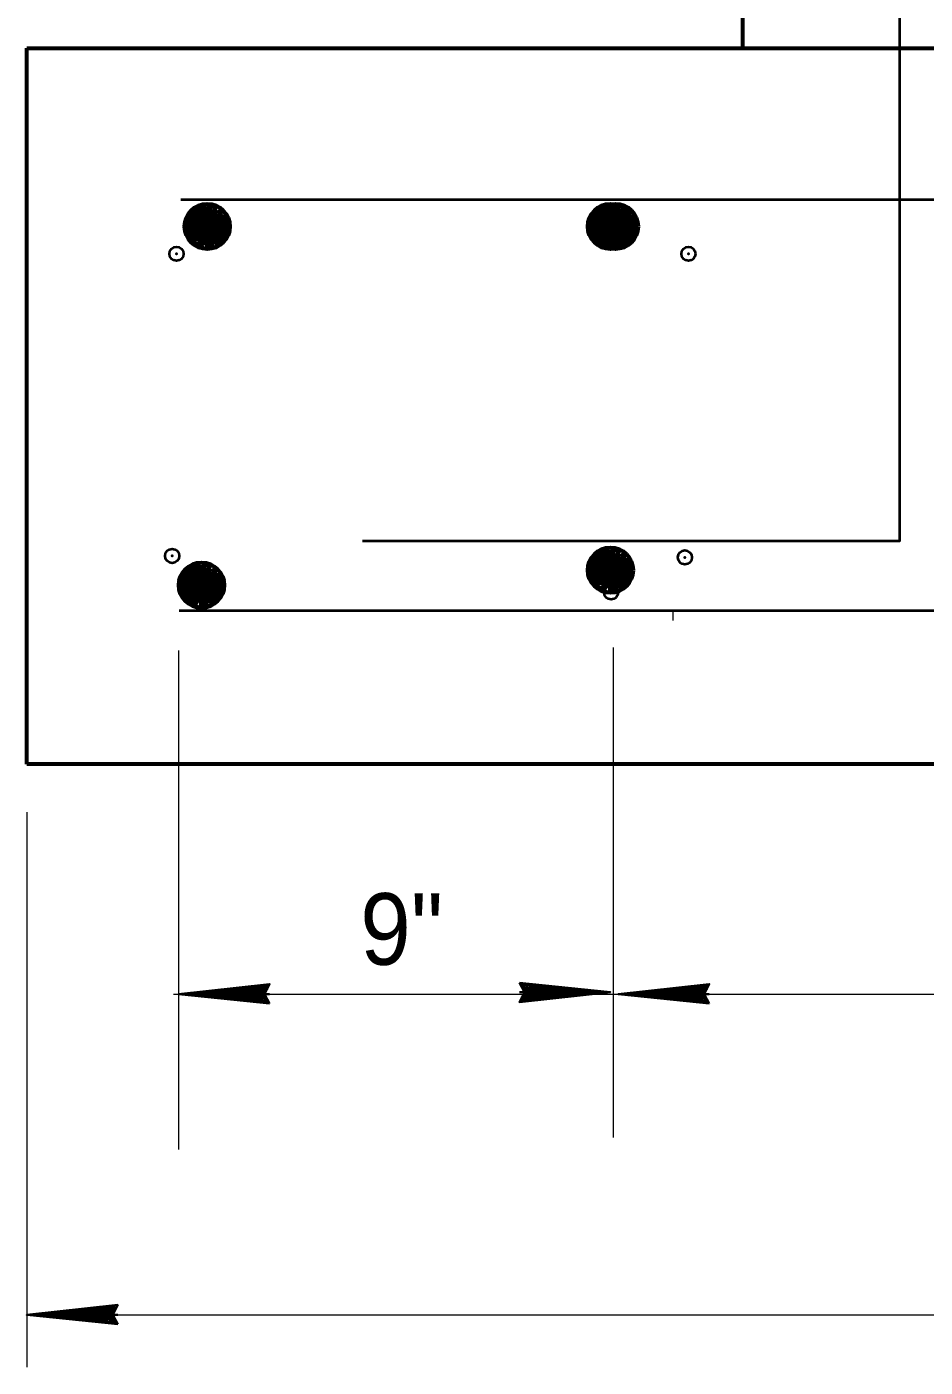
# Model space of a CAD drawing. Extents: x 14.14 to 17.34, y -1.61 to 0.38.
# Drawn here: x 15.5065 to 15.611, y -0.0853 to 0.0707 of the extents above; entities that cross this region are included whole.
import ezdxf
from ezdxf.enums import TextEntityAlignment as Align

# ---------------------------------------------------------------- set-up
doc = ezdxf.new("R2010")
doc.units = 0
doc.header["$LTSCALE"] = 0.0033
doc.header["$PDMODE"] = 32
doc.header["$PDSIZE"] = 0.00165
doc.layers.add('1', color=7, linetype='Continuous', lineweight=40)

msp = doc.modelspace()

# ---------------------------------------------------------------- linework, layer by layer
at = {"layer": '1', "lineweight": 60}
for p, q in [((15.5065, -0.015167), (15.5065, 0.068167)), ((15.589833, 0.068167), (15.652333, 0.068167)), ((15.525667, 0.049), (15.5255, 0.046083)), ((15.525917, 0.049), (15.525667, 0.046083)), ((15.526083, 0.049), (15.525917, 0.046)), ((15.52625, 0.049), (15.526, 0.046)), ((15.526417, 0.049), (15.52625, 0.046)), ((15.526667, 0.049), (15.5265, 0.046)), ((15.526917, 0.049), (15.526667, 0.046)), ((15.527, 0.048917), (15.526833, 0.046)), ((15.527167, 0.048917), (15.527, 0.046)), ((15.527333, 0.048917), (15.527167, 0.046)), ((15.527583, 0.048917), (15.527333, 0.046)), ((15.52775, 0.048917), (15.527583, 0.046)), ((15.528, 0.048833), (15.52775, 0.045917)), ((15.52825, 0.048833), (15.528, 0.045917)), ((15.528417, 0.048833), (15.52825, 0.045917)), ((15.5285, 0.048833), (15.528333, 0.045917)), ((15.528667, 0.048833), (15.5285, 0.045917)), ((15.52875, 0.048833), (15.528583, 0.045917)), ((15.529, 0.04875), (15.52875, 0.045833)), ((15.529167, 0.04875), (15.529, 0.045833)), ((15.529333, 0.04875), (15.529083, 0.045833)), ((15.5295, 0.04875), (15.529333, 0.045833)), ((15.52975, 0.04875), (15.529583, 0.045833)), ((15.53, 0.046833), (15.529833, 0.048667)), ((15.572583, 0.049), (15.572417, 0.046083)), ((15.572833, 0.049), (15.572583, 0.046083)), ((15.573, 0.049), (15.572833, 0.046)), ((15.573167, 0.049), (15.572917, 0.046)), ((15.573167, 0.049), (15.573, 0.046083)), ((15.573417, 0.049), (15.573167, 0.046083)), ((15.573333, 0.049), (15.573167, 0.046)), ((15.573583, 0.049), (15.573417, 0.046)), ((15.573583, 0.049), (15.573417, 0.046)), ((15.57375, 0.049), (15.5735, 0.046)), ((15.573833, 0.049), (15.573583, 0.046)), ((15.573917, 0.049), (15.57375, 0.046)), ((15.573917, 0.048917), (15.57375, 0.046)), ((15.574083, 0.048917), (15.573917, 0.046)), ((15.574167, 0.049), (15.574, 0.046)), ((15.57425, 0.048917), (15.574083, 0.046)), ((15.574417, 0.049), (15.574167, 0.046)), ((15.5745, 0.048917), (15.57425, 0.046)), ((15.5745, 0.048917), (15.574333, 0.046)), ((15.574667, 0.048917), (15.5745, 0.046)), ((15.574667, 0.048917), (15.5745, 0.046)), ((15.574833, 0.048917), (15.574667, 0.046)), ((15.574917, 0.048833), (15.574667, 0.045917)), ((15.575083, 0.048917), (15.574833, 0.046)), ((15.575167, 0.048833), (15.574917, 0.045917)), ((15.57525, 0.048917), (15.575083, 0.046)), ((15.575333, 0.048833), (15.575167, 0.045917)), ((15.5755, 0.048833), (15.57525, 0.045917)), ((15.575417, 0.048833), (15.57525, 0.045917)), ((15.575583, 0.048833), (15.575417, 0.045917)), ((15.57575, 0.048833), (15.5755, 0.045917)), ((15.575667, 0.048833), (15.5755, 0.045917)), ((15.575917, 0.04875), (15.575667, 0.045833)), ((15.575917, 0.048833), (15.57575, 0.045917)), ((15.576, 0.048833), (15.575833, 0.045917)), ((15.576083, 0.04875), (15.575917, 0.045833)), ((15.576167, 0.048833), (15.576, 0.045917)), ((15.57625, 0.04875), (15.576, 0.045833)), ((15.57625, 0.048833), (15.576083, 0.045917)), ((15.5765, 0.04875), (15.57625, 0.045833)), ((15.576417, 0.04875), (15.57625, 0.045833)), ((15.576667, 0.04875), (15.5765, 0.045833)), ((15.576667, 0.04875), (15.5765, 0.045833)), ((15.576833, 0.04875), (15.576583, 0.045833)), ((15.576917, 0.046833), (15.57675, 0.048667)), ((15.577, 0.04875), (15.576833, 0.045833)), ((15.57725, 0.04875), (15.577083, 0.045833)), ((15.5775, 0.046833), (15.577333, 0.048667)), ((15.53, 0.046833), (15.52525, 0.046083)), ((15.576917, 0.046833), (15.572167, 0.046083)), ((15.5775, 0.046833), (15.57275, 0.046083)), ((15.572583, 0.009), (15.572417, 0.006083)), ((15.572833, 0.009), (15.572583, 0.006083)), ((15.573, 0.009), (15.572833, 0.006)), ((15.573167, 0.009), (15.572917, 0.006)), ((15.573333, 0.009), (15.573167, 0.006)), ((15.573583, 0.009), (15.573417, 0.006)), ((15.573833, 0.009), (15.573583, 0.006)), ((15.573917, 0.008917), (15.57375, 0.006)), ((15.574083, 0.008917), (15.573917, 0.006)), ((15.57425, 0.008917), (15.574083, 0.006)), ((15.5745, 0.008917), (15.57425, 0.006)), ((15.574667, 0.008917), (15.5745, 0.006)), ((15.574917, 0.008833), (15.574667, 0.005917)), ((15.575167, 0.008833), (15.574917, 0.005917)), ((15.575333, 0.008833), (15.575167, 0.005917)), ((15.575417, 0.008833), (15.57525, 0.005917)), ((15.575583, 0.008833), (15.575417, 0.005917)), ((15.575667, 0.008833), (15.5755, 0.005917)), ((15.575917, 0.00875), (15.575667, 0.005833)), ((15.576083, 0.00875), (15.575917, 0.005833)), ((15.57625, 0.00875), (15.576, 0.005833)), ((15.576417, 0.00875), (15.57625, 0.005833)), ((15.576667, 0.00875), (15.5765, 0.005833)), ((15.576917, 0.006833), (15.57675, 0.008667)), ((15.525, 0.00725), (15.524833, 0.004333)), ((15.52525, 0.00725), (15.525, 0.004333)), ((15.525417, 0.00725), (15.52525, 0.00425)), ((15.525583, 0.00725), (15.525333, 0.00425)), ((15.52575, 0.00725), (15.525583, 0.00425)), ((15.526, 0.00725), (15.525833, 0.00425)), ((15.52625, 0.00725), (15.526, 0.00425)), ((15.526333, 0.007167), (15.526167, 0.00425)), ((15.5265, 0.007167), (15.526333, 0.00425)), ((15.526667, 0.007167), (15.5265, 0.00425)), ((15.526917, 0.007167), (15.526667, 0.00425)), ((15.527083, 0.007167), (15.526917, 0.00425)), ((15.527333, 0.007083), (15.527083, 0.004167)), ((15.527583, 0.007083), (15.527333, 0.004167)), ((15.52775, 0.007083), (15.527583, 0.004167)), ((15.527833, 0.007083), (15.527667, 0.004167)), ((15.528, 0.007083), (15.527833, 0.004167)), ((15.528083, 0.007083), (15.527917, 0.004167)), ((15.528333, 0.007), (15.528083, 0.004083)), ((15.5285, 0.007), (15.528333, 0.004083)), ((15.528667, 0.007), (15.528417, 0.004083)), ((15.528833, 0.007), (15.528667, 0.004083)), ((15.529083, 0.007), (15.528917, 0.004083)), ((15.529333, 0.005083), (15.529167, 0.006917)), ((15.576917, 0.006833), (15.572167, 0.006083)), ((15.529333, 0.005083), (15.524583, 0.004333))]:
    msp.add_line(p, q, dxfattribs=at)
at = {"layer": '1'}
for p, q in [((15.524417, 0.050583), (15.822167, 0.050583)), ((15.525417, 0.049), (15.53, 0.046833)), ((15.525667, 0.048583), (15.529583, 0.047833)), ((15.525667, 0.048417), (15.529583, 0.047667)), ((15.52575, 0.049), (15.529667, 0.048333)), ((15.52575, 0.048833), (15.529667, 0.048083)), ((15.525833, 0.049333), (15.529667, 0.048667)), ((15.52775, 0.0485), (15.529083, 0.0495)), ((15.529833, 0.048667), (15.528583, 0.049833)), ((15.572333, 0.049), (15.576917, 0.046833)), ((15.572583, 0.048583), (15.5765, 0.047833)), ((15.572583, 0.048417), (15.5765, 0.047667)), ((15.572667, 0.049), (15.576583, 0.048333)), ((15.572667, 0.048833), (15.576583, 0.048083)), ((15.57275, 0.049333), (15.576583, 0.048667)), ((15.572917, 0.049), (15.5775, 0.046833)), ((15.573167, 0.048583), (15.577083, 0.047833)), ((15.573167, 0.048417), (15.577083, 0.047667)), ((15.57325, 0.049), (15.577167, 0.048333)), ((15.57325, 0.048833), (15.577167, 0.048083)), ((15.573333, 0.049333), (15.577167, 0.048667)), ((15.574667, 0.0485), (15.576, 0.0495)), ((15.57525, 0.0485), (15.576583, 0.0495)), ((15.57675, 0.048667), (15.5755, 0.049833)), ((15.577333, 0.048667), (15.576083, 0.049833)), ((15.525417, 0.047167), (15.529333, 0.046417)), ((15.5255, 0.047583), (15.529333, 0.046833)), ((15.5255, 0.047417), (15.529333, 0.046667)), ((15.525583, 0.048), (15.529417, 0.047333)), ((15.525583, 0.047833), (15.529417, 0.047083)), ((15.525667, 0.048167), (15.5295, 0.047417)), ((15.572333, 0.047167), (15.57625, 0.046417)), ((15.572417, 0.047583), (15.57625, 0.046833)), ((15.572417, 0.047417), (15.57625, 0.046667)), ((15.5725, 0.048), (15.576333, 0.047333)), ((15.5725, 0.047833), (15.576333, 0.047083)), ((15.572583, 0.048167), (15.576417, 0.047417)), ((15.572917, 0.047167), (15.576833, 0.046417)), ((15.573, 0.047583), (15.576833, 0.046833)), ((15.573, 0.047417), (15.576833, 0.046667)), ((15.573083, 0.048), (15.576917, 0.047333)), ((15.573083, 0.047833), (15.576917, 0.047083)), ((15.573167, 0.048167), (15.577, 0.047417)), ((15.52525, 0.04625), (15.529083, 0.0455)), ((15.52525, 0.046083), (15.529083, 0.045333)), ((15.525333, 0.04675), (15.52925, 0.046)), ((15.525333, 0.046583), (15.529167, 0.045833)), ((15.525333, 0.046333), (15.529167, 0.045667)), ((15.529583, 0.045833), (15.525833, 0.045417)), ((15.572167, 0.04625), (15.576, 0.0455)), ((15.572167, 0.046083), (15.576, 0.045333)), ((15.57225, 0.04675), (15.576167, 0.046)), ((15.57225, 0.046583), (15.576083, 0.045833)), ((15.57225, 0.046333), (15.576083, 0.045667)), ((15.57275, 0.04625), (15.576583, 0.0455)), ((15.57275, 0.046083), (15.576583, 0.045333)), ((15.5765, 0.045833), (15.57275, 0.045417)), ((15.572833, 0.04675), (15.57675, 0.046)), ((15.572833, 0.046583), (15.576667, 0.045833)), ((15.572833, 0.046333), (15.576667, 0.045667)), ((15.577083, 0.045833), (15.573333, 0.045417)), ((15.574667, 0.0085), (15.576, 0.0095)), ((15.57675, 0.008667), (15.5755, 0.009833)), ((15.529167, 0.006917), (15.527917, 0.008083)), ((15.572333, 0.009), (15.576917, 0.006833)), ((15.5725, 0.008), (15.576333, 0.007333)), ((15.5725, 0.007833), (15.576333, 0.007083)), ((15.572583, 0.008583), (15.5765, 0.007833)), ((15.572583, 0.008417), (15.5765, 0.007667)), ((15.572583, 0.008167), (15.576417, 0.007417)), ((15.572667, 0.009), (15.576583, 0.008333)), ((15.572667, 0.008833), (15.576583, 0.008083)), ((15.57275, 0.009333), (15.576583, 0.008667)), ((15.52475, 0.00725), (15.529333, 0.005083)), ((15.524917, 0.00625), (15.52875, 0.005583)), ((15.525, 0.006833), (15.528917, 0.006083)), ((15.525, 0.006667), (15.528917, 0.005917)), ((15.525, 0.006417), (15.528833, 0.005667)), ((15.525083, 0.00725), (15.529, 0.006583)), ((15.525083, 0.007083), (15.529, 0.006333)), ((15.525167, 0.007583), (15.529, 0.006917)), ((15.527083, 0.00675), (15.528417, 0.00775)), ((15.572167, 0.00625), (15.576, 0.0055)), ((15.57225, 0.00675), (15.576167, 0.006)), ((15.57225, 0.006583), (15.576083, 0.005833)), ((15.57225, 0.006333), (15.576083, 0.005667)), ((15.572333, 0.007167), (15.57625, 0.006417)), ((15.572417, 0.007583), (15.57625, 0.006833)), ((15.572417, 0.007417), (15.57625, 0.006667)), ((15.524667, 0.005), (15.528583, 0.00425)), ((15.524667, 0.004833), (15.5285, 0.004083)), ((15.52475, 0.005417), (15.528667, 0.004667)), ((15.524833, 0.005833), (15.528667, 0.005083)), ((15.524833, 0.005667), (15.528667, 0.004917)), ((15.524917, 0.006083), (15.52875, 0.005333)), ((15.572167, 0.006083), (15.576, 0.005333)), ((15.5765, 0.005833), (15.57275, 0.005417)), ((15.524583, 0.0045), (15.528417, 0.00375)), ((15.524583, 0.004333), (15.528417, 0.003583)), ((15.524667, 0.004583), (15.5285, 0.003917)), ((15.528917, 0.004083), (15.525167, 0.003667)), ((15.52425, 0.00275), (15.821917, 0.00275))]:
    msp.add_line(p, q, dxfattribs=at)
at = {"layer": '1', "lineweight": 13}
for p, q in [((15.581667, 0.00275), (15.581667, 0.001583)), ((15.524167, -0.001917), (15.524167, -0.06)), ((15.57475, -0.001583), (15.57475, -0.058583)), ((15.5065, -0.02075), (15.5065, -0.085333)), ((15.523583, -0.041917), (15.820833, -0.041917)), ((15.511083, -0.07925), (15.837333, -0.07925))]:
    msp.add_line(p, q, dxfattribs=at)
at = {"layer": '1', "lineweight": 35}
for p, q in [((15.53475, -0.041917), (15.524167, -0.041917)), ((15.5345, -0.04275), (15.526667, -0.04175)), ((15.5345, -0.04275), (15.526667, -0.041917)), ((15.5345, -0.042917), (15.526667, -0.042)), ((15.5345, -0.042917), (15.526667, -0.042)), ((15.5345, -0.042833), (15.526667, -0.042)), ((15.5345, -0.040833), (15.527167, -0.041667)), ((15.5345, -0.041), (15.527167, -0.04175)), ((15.5345, -0.041083), (15.527167, -0.041917)), ((15.534583, -0.04125), (15.52725, -0.042)), ((15.563833, -0.041667), (15.574417, -0.041667)), ((15.564, -0.042333), (15.571333, -0.041583)), ((15.564083, -0.040667), (15.571917, -0.041583)), ((15.564083, -0.040667), (15.571917, -0.041583)), ((15.564083, -0.04075), (15.571917, -0.041583)), ((15.564083, -0.040833), (15.571917, -0.041667)), ((15.564083, -0.040833), (15.571917, -0.041833)), ((15.564083, -0.0425), (15.571417, -0.041667)), ((15.564083, -0.042583), (15.571417, -0.041833)), ((15.564083, -0.04275), (15.571417, -0.041917)), ((15.585917, -0.041917), (15.575333, -0.041917)), ((15.585667, -0.04275), (15.577833, -0.04175)), ((15.585667, -0.04275), (15.577833, -0.041917)), ((15.585667, -0.042917), (15.577833, -0.042)), ((15.585667, -0.042917), (15.577833, -0.042)), ((15.585667, -0.042833), (15.577833, -0.042)), ((15.585667, -0.040833), (15.578333, -0.041667)), ((15.585667, -0.041), (15.578333, -0.04175)), ((15.585667, -0.041083), (15.578333, -0.041917)), ((15.58575, -0.04125), (15.578417, -0.042)), ((15.517083, -0.07925), (15.5065, -0.07925)), ((15.516833, -0.080083), (15.509, -0.079083)), ((15.516833, -0.080083), (15.509, -0.07925)), ((15.516833, -0.08025), (15.509, -0.079333)), ((15.516833, -0.08025), (15.509, -0.079333)), ((15.516833, -0.080167), (15.509, -0.079333)), ((15.516833, -0.078167), (15.5095, -0.079)), ((15.516833, -0.078333), (15.5095, -0.079083)), ((15.516833, -0.078417), (15.5095, -0.07925)), ((15.516917, -0.078583), (15.509583, -0.079333))]:
    msp.add_line(p, q, dxfattribs=at)
at = {"layer": '1', "lineweight": 60}
for points in [[(15.5065, 0.068167), (15.589833, 0.068167), (15.589833, 0.172333)], [(15.839833, 0.068167), (15.839833, -0.015167), (15.5065, -0.015167)], [(15.529083, 0.045333), (15.529083, 0.0495), (15.527417, 0.044833), (15.527917, 0.05), (15.525833, 0.045417), (15.526583, 0.049917), (15.528167, 0.044917), (15.525, 0.04825), (15.529833, 0.048667), (15.526583, 0.045), (15.528583, 0.049833), (15.525417, 0.049), (15.52525, 0.046083)], [(15.525833, 0.045417), (15.527333, 0.047667), (15.525167, 0.048583), (15.527167, 0.05), (15.527333, 0.04775), (15.529, 0.045417), (15.525, 0.04775), (15.52775, 0.0485)], [(15.576, 0.045333), (15.576, 0.0495), (15.574333, 0.044833), (15.574833, 0.05), (15.57275, 0.045417), (15.5735, 0.049917), (15.575083, 0.044917), (15.571917, 0.04825), (15.57675, 0.048667), (15.5735, 0.045), (15.5755, 0.049833), (15.572333, 0.049), (15.572167, 0.046083)], [(15.57275, 0.045417), (15.57425, 0.047667), (15.572083, 0.048583), (15.574083, 0.05), (15.57425, 0.04775), (15.575917, 0.045417), (15.571917, 0.04775), (15.574667, 0.0485)], [(15.576583, 0.045333), (15.576583, 0.0495), (15.574917, 0.044833), (15.575417, 0.05), (15.573333, 0.045417), (15.574083, 0.049917), (15.575667, 0.044917), (15.5725, 0.04825), (15.577333, 0.048667), (15.574083, 0.045), (15.576083, 0.049833), (15.572917, 0.049), (15.57275, 0.046083)], [(15.573333, 0.045417), (15.574833, 0.047667), (15.572667, 0.048583), (15.574667, 0.05), (15.574833, 0.04775), (15.5765, 0.045417), (15.5725, 0.04775), (15.57525, 0.0485)], [(15.524833, 0.047333), (15.53, 0.048), (15.525417, 0.049)], [(15.528583, 0.049833), (15.527333, 0.047667), (15.529583, 0.045833)], [(15.57175, 0.047333), (15.576917, 0.048), (15.572333, 0.049)], [(15.572333, 0.047333), (15.5775, 0.048), (15.572917, 0.049)], [(15.5755, 0.049833), (15.57425, 0.047667), (15.5765, 0.045833)], [(15.576083, 0.049833), (15.574833, 0.047667), (15.577083, 0.045833)], [(15.576, 0.005333), (15.576, 0.0095), (15.574333, 0.004833), (15.574833, 0.01), (15.57275, 0.005417), (15.5735, 0.009917), (15.575083, 0.004917), (15.571917, 0.00825), (15.57675, 0.008667), (15.5735, 0.005), (15.5755, 0.009833), (15.572333, 0.009), (15.572167, 0.006083)], [(15.57275, 0.005417), (15.57425, 0.007667), (15.572083, 0.008583), (15.574083, 0.01), (15.57425, 0.00775), (15.575917, 0.005417), (15.571917, 0.00775), (15.574667, 0.0085)], [(15.5755, 0.009833), (15.57425, 0.007667), (15.5765, 0.005833)], [(15.528417, 0.003583), (15.528417, 0.00775), (15.52675, 0.003083), (15.52725, 0.00825), (15.525167, 0.003667), (15.525917, 0.008167), (15.5275, 0.003167), (15.524333, 0.0065), (15.529167, 0.006917), (15.525917, 0.00325), (15.527917, 0.008083), (15.52475, 0.00725), (15.524583, 0.004333)], [(15.525167, 0.003667), (15.526667, 0.005917), (15.5245, 0.006833), (15.5265, 0.00825), (15.526667, 0.006), (15.528333, 0.003667), (15.524333, 0.006), (15.527083, 0.00675)], [(15.527917, 0.008083), (15.526667, 0.005917), (15.528917, 0.004083)], [(15.57175, 0.007333), (15.576917, 0.008), (15.572333, 0.009)], [(15.524167, 0.005583), (15.529333, 0.00625), (15.52475, 0.00725)]]:
    msp.add_lwpolyline(points, dxfattribs=at)
at = {"layer": '1'}
for points in [[(15.545583, 0.010833), (15.608083, 0.010833), (15.608083, 0.123)], [(15.52525, 0.046083), (15.527333, 0.044833), (15.529083, 0.045333), (15.53, 0.046833)], [(15.572167, 0.046083), (15.57425, 0.044833), (15.576, 0.045333), (15.576917, 0.046833)], [(15.57275, 0.046083), (15.574833, 0.044833), (15.576583, 0.045333), (15.5775, 0.046833)], [(15.572167, 0.006083), (15.57425, 0.004833), (15.576, 0.005333), (15.576917, 0.006833)], [(15.524583, 0.004333), (15.526667, 0.003083), (15.528417, 0.003583), (15.529333, 0.005083)]]:
    msp.add_lwpolyline(points, dxfattribs=at)
at = {"layer": '1', "lineweight": 35}
for points in [[(15.53475, -0.043), (15.524167, -0.041917), (15.53475, -0.04075), (15.534167, -0.041917)], [(15.534, -0.042), (15.529333, -0.042083), (15.529333, -0.042), (15.53025, -0.042), (15.534, -0.042083), (15.531, -0.042167), (15.534167, -0.04225), (15.531917, -0.042333), (15.534167, -0.042417), (15.530667, -0.042167), (15.526, -0.042), (15.526917, -0.04175), (15.525667, -0.04175), (15.534, -0.04175), (15.531583, -0.041583), (15.534167, -0.041583), (15.528833, -0.042), (15.534167, -0.041333)], [(15.563833, -0.040583), (15.574417, -0.041667), (15.563833, -0.042833), (15.564417, -0.041667)], [(15.564583, -0.041583), (15.56925, -0.0415), (15.56925, -0.041583), (15.568333, -0.041583), (15.564583, -0.0415), (15.567583, -0.041417), (15.564417, -0.041333), (15.566667, -0.04125), (15.564417, -0.041167), (15.567917, -0.041417), (15.572583, -0.041583), (15.571667, -0.041833), (15.572917, -0.041833), (15.564583, -0.041833), (15.567, -0.042), (15.564417, -0.042), (15.56975, -0.041583), (15.564417, -0.04225)], [(15.585917, -0.043), (15.575333, -0.041917), (15.585917, -0.04075), (15.585333, -0.041917)], [(15.585167, -0.042), (15.5805, -0.042083), (15.5805, -0.042), (15.581417, -0.042), (15.585167, -0.042083), (15.582167, -0.042167), (15.585333, -0.04225), (15.583083, -0.042333), (15.585333, -0.042417), (15.581833, -0.042167), (15.577167, -0.042), (15.578083, -0.04175), (15.576833, -0.04175), (15.585167, -0.04175), (15.58275, -0.041583), (15.585333, -0.041583), (15.58, -0.042), (15.585333, -0.041333)], [(15.517083, -0.080333), (15.5065, -0.07925), (15.517083, -0.078083), (15.5165, -0.07925)], [(15.516333, -0.079333), (15.511667, -0.079417), (15.511667, -0.079333), (15.512583, -0.079333), (15.516333, -0.079417), (15.513333, -0.0795), (15.5165, -0.079583), (15.51425, -0.079667), (15.5165, -0.07975), (15.513, -0.0795), (15.508333, -0.079333), (15.50925, -0.079083), (15.508, -0.079083), (15.516333, -0.079083), (15.513917, -0.078917), (15.5165, -0.078917), (15.511167, -0.079333), (15.5165, -0.078667)]]:
    msp.add_lwpolyline(points, close=True, dxfattribs=at)
for points in [[(15.534, -0.042), (15.534417, -0.04275), (15.534167, -0.0425), (15.534, -0.042167), (15.53375, -0.04225), (15.533917, -0.042583), (15.534083, -0.041833), (15.53425, -0.041333), (15.5345, -0.040917)], [(15.564583, -0.041583), (15.564167, -0.040833), (15.564417, -0.041083), (15.564583, -0.041417), (15.564833, -0.041333), (15.564667, -0.041), (15.5645, -0.04175), (15.564333, -0.04225), (15.564083, -0.042667)], [(15.585167, -0.042), (15.585583, -0.04275), (15.585333, -0.0425), (15.585167, -0.042167), (15.584917, -0.04225), (15.585083, -0.042583), (15.58525, -0.041833), (15.585417, -0.041333), (15.585667, -0.040917)], [(15.516333, -0.079333), (15.51675, -0.080083), (15.5165, -0.079833), (15.516333, -0.0795), (15.516083, -0.079583), (15.51625, -0.079917), (15.516417, -0.079167), (15.516583, -0.078667), (15.516833, -0.07825)]]:
    msp.add_lwpolyline(points, dxfattribs=at)
at = {"layer": '1', "lineweight": 60}
for centre in [(15.5275, 0.047433), (15.574417, 0.047433), (15.575, 0.047433), (15.574417, 0.007433), (15.526833, 0.005683)]:
    msp.add_circle(centre, 0.00264, dxfattribs=at)
at = {"layer": '1'}
for p in [(15.526917, 0.046417), (15.523917, 0.04425), (15.5835, 0.04425), (15.523417, 0.009083), (15.583083, 0.008917), (15.526333, 0.005833), (15.52575, 0.004667), (15.5745, 0.004833)]:
    msp.add_point(p, dxfattribs=at)

# ---------------------------------------------------------------- texts
at = {"layer": '1', "width": 0.95}
msp.add_text('9"', height=0.008334, dxfattribs=at).set_placement((15.550125, -0.0385), align=Align.CENTER)

doc.saveas('drawing.dxf')
